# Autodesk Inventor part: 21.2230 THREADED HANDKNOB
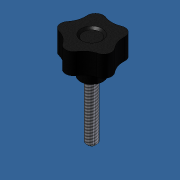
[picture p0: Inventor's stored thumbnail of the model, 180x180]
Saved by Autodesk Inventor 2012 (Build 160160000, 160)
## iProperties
Created: 2013-10
Part Number: 21.2230 THREADED HANDKNOB
Material: ABS Plastic
Document SubType Name: Modeling
Designer: Admin
Density: 1.06 g/cm^3
Mass: 16.9376 g
Surface Area: 75.8851 cm^2
Volume: 15.9789 cm^3
Author: Admin
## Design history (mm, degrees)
sketch "Sketch1"
  geometry: C1 r 7 at (0, 0) reference; A1 r 16.053 centre (18.916, -25.544) between (14.249, -10.185) and (5.233, -17.15) reference; A2 r 6.05 centre (13.291, -4.211) between (14.249, -10.185) and (18.024, -0.442) reference; A3 r 16.195 centre (30.281, 10.143) between (14.121, 11.217) and (18.024, -0.442) reference; A4 r 6 centre (8.124, 11.399) between (14.121, 11.217) and (5.847, 16.95) reference; A5 r 16.095 centre (-0.304, 31.823) between (-6.455, 16.95) and (5.847, 16.95) reference; A6 r 6.003 centre (-8.328, 11.248) between (-6.455, 16.95) and (-14.314, 10.799) reference; A7 r 16.063 centre (-30.329, 9.552) between (-17.919, -0.647) and (-14.314, 10.799) reference; A8 r 6.014 centre (-13.259, -4.45) between (-17.919, -0.647) and (-14.374, -10.36) reference; A9 r 15.994 centre (-18.415, -25.835) between (-5.102, -16.971) and (-14.374, -10.36) reference; A10 r 6.016 centre (0.119, -13.982) between (-5.102, -16.971) and (5.233, -17.15) reference; 2 further points
  constraints: 20 point on circle, 11 centre point, 33 other
extrude "Extrusion1" new body sketch "Sketch1" distance "d11" = 16; taper "d12" = 0 deg
sketch "Sketch2"
  geometry: C1 r 8 at (0, 0); 1 further point
  constraints: 1 centre point, 1 coincident
  dimensions: "d13" = 16 diameter of C1
extrude "Extrusion2" cut sketch "Sketch2" distance "d14" = 1.5; taper "d15" = -45 deg
shell "Shell1" dims "d16" = 3.5
sketch "Sketch3"
  geometry: C1 r 9.45 at (-0.175, -31.824) reference; C2 r 9.5 at (-0.175, -31.824)
  constraints: 1 centre point, 1 coincident
  dimensions: "d17" = 19 diameter of C2
extrude "Extrusion3" join sketch "Sketch3" distance "d18" = 8.5; taper "d19" = -4 deg
sketch "Sketch4"
  geometry: C1 r 8.855 at (0, 0) reference; C2 r 8.5 at (0, 0)
  constraints: 1 centre point, 1 coincident
  dimensions: "d20" = 17 diameter of C2
extrude "Extrusion4" join sketch "Sketch4" distance "d21" = 15; taper "d22" = 0 deg
sketch "Sketch5"
  geometry: C1 r 8.5 at (0, 0) reference; C2 r 4 at (0, 0)
  constraints: 1 centre point, 1 coincident
  dimensions: "d23" = 8 diameter of C2
extrude "Extrusion5" join sketch "Sketch5" distance "d24" = 45; taper "d25" = 0 deg
chamfer "Chamfer1" distance "d26" = 1.5; stored, may be unused: second distance "d27" = 2, angle "d28" = 45 deg
body "Solid1"
